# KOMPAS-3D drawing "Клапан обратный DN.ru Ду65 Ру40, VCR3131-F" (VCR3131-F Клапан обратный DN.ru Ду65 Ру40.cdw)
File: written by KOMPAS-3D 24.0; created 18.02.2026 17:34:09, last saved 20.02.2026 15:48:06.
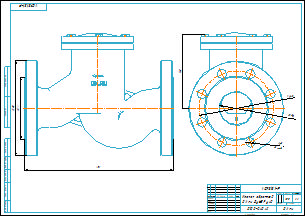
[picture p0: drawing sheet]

Document properties: art: D100-04042; Автор: R2D2; Форматы листов документа: A2; Полное имя файла: VCR3131-F Клапан обратный DN.ru Ду65 Ру40.m3d; Масса: 15.5; Наименование: Клапан обратный DN.ru Ду65 Ру40; Количество листов документа: 1; Примечание: D100-04042

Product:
- Part/product: Клапан обратный DN.ru Ду65 Ру40  | designation VCR3131-F
    Масса: 15.5
    Примечание: D100-04042
    additional columns: D100-04042

Views: Вид 1, Спереди, Проекционный вид 2
Referenced files in E:\Работа\Зайцев\VCR3131-F Клапан обратный DN.ru Ду15-300\DN65\: VCR3131-F Клапан обратный DN.ru Ду65 Ру40.m3d
Referenced files in E:\Работа\Зайцев\Для компаса\: чертеж DN.ru А3.cdt
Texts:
  VCR3131-F
  чертеж DN.ru А3.cdt
  Клапан обратный
  DN.ru Ду65 Ру40
  prop
  Клапан обратный DN.ru Ду65 Ру40
  VCR3131-F Клапан обратный DN.ru Ду65 Ру40
Dimensions and other numbers on the sheet: 0; 3; 2; 4; 145; 65; 18; 8 отв.; 290; 185; 122; 1:1; 1; 15,5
